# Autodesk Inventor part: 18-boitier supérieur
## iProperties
Created: 2011-02
Part Number: 18-boitier supérieur
Document SubType Name: Modeling
Designer: eric
Density: 1 g/cm^3
Author: eric
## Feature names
1. Base1
